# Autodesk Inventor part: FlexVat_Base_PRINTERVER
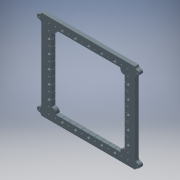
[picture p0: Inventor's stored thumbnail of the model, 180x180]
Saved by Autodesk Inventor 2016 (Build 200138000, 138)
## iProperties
Created: 2015-11
Part Number: FlexVat_Base_PRINTERVER
Material: Generic
Document SubType Name: Modeling
Designer: John
Density: 1 g/cm^3
Appearance: Default
Author: John
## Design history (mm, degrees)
feature "Base1"
sketch "Sketch1"
  geometry: L1 (212.7, 0)-(0, 0) reference; L2 (0, -20)-(0, -182.7) reference; L3 (0, -202.7)-(212.7, -202.7) reference; L4 (212.7, -20)-(212.7, -182.7) reference; L5 (18.082, -26.891)-(18.082, -26.392) reference; L6 (31.388, -189.618)-(31.888, -189.618) reference; L7 (180.808, -13.082)-(181.308, -13.082) reference; L8 (194.618, -26.392)-(194.618, -26.89) reference; L9 (189.575, -27.906)-(189.575, -41.33) reference; L10 (192.608, -41.33)-(189.575, -41.33) reference; L11 (189.575, -41.834)-(192.609, -41.834) reference; L12 (189.575, -41.834)-(189.575, -56.276) reference; L13 (194.617, -56.276)-(189.575, -56.276) reference; L14 (189.575, -56.776)-(194.619, -56.776) reference; L15 (189.575, -56.776)-(189.575, -71.214) reference; L16 (192.608, -71.214)-(189.575, -71.214) reference; L17 (189.575, -71.718)-(192.609, -71.718) reference; L18 (189.575, -71.718)-(189.575, -86.156) reference; L19 (189.575, -86.156)-(194.619, -86.156) reference; L20 (194.618, -86.66)-(189.575, -86.66) reference; L21 (189.575, -86.66)-(189.575, -101.102) reference; L22 (192.608, -101.102)-(189.575, -101.102) reference; L23 (189.575, -101.602)-(192.609, -101.602) reference; L24 (189.575, -101.602)-(189.575, -116.04) reference; L25 (189.575, -116.04)-(194.619, -116.04) reference; L26 (194.618, -116.544)-(189.575, -116.544) reference; L27 (189.575, -116.544)-(189.575, -130.982) reference; L28 (189.575, -130.982)-(192.609, -130.982) reference; L29 (192.608, -131.486)-(189.575, -131.486) reference; L30 (189.575, -131.486)-(189.575, -145.928) reference; L31 (189.575, -145.928)-(194.618, -145.928) reference; L32 (194.618, -146.428)-(189.575, -146.428) reference; L33 (189.575, -146.428)-(189.575, -160.866) reference; L34 (192.608, -160.866)-(189.575, -160.866) reference; L35 (189.575, -161.37)-(192.609, -161.37) reference; L36 (189.575, -161.37)-(189.575, -174.794) reference; L37 (179.794, -184.575)-(166.366, -184.575) reference; L38 (166.366, -184.575)-(166.366, -187.608) reference; L39 (165.866, -187.608)-(165.866, -184.575) reference; L40 (165.866, -184.575)-(151.424, -184.575) reference; L41 (151.424, -184.575)-(151.424, -189.618) reference; L42 (150.924, -189.618)-(150.924, -184.575) reference; L43 (150.924, -184.575)-(136.482, -184.575) reference; L44 (136.482, -184.575)-(136.482, -187.608) reference; L45 (135.982, -187.608)-(135.982, -184.575) reference; L46 (135.982, -184.575)-(121.54, -184.575) reference; L47 (121.54, -184.575)-(121.54, -189.618) reference; L48 (121.04, -189.618)-(121.04, -184.575) reference; L49 (121.04, -184.575)-(106.598, -184.575) reference; L50 (106.598, -184.575)-(106.598, -187.608) reference; L51 (106.098, -187.608)-(106.098, -184.575) reference; L52 (106.098, -184.575)-(91.656, -184.575) reference; L53 (91.656, -184.575)-(91.656, -189.618) reference; L54 (91.156, -189.618)-(91.156, -184.575) reference; L55 (91.156, -184.575)-(76.714, -184.575) reference; L56 (76.714, -184.575)-(76.714, -187.608) reference; L57 (76.214, -187.608)-(76.214, -184.575) reference; L58 (76.214, -184.575)-(61.772, -184.575) reference; L59 (61.772, -184.575)-(61.772, -189.618) reference; L60 (61.272, -189.618)-(61.272, -184.575) reference; L61 (61.272, -184.575)-(46.83, -184.575) reference; L62 (46.83, -184.575)-(46.83, -187.608) reference; L63 (46.33, -187.608)-(46.33, -184.575) reference; L64 (46.33, -184.575)-(32.906, -184.575) reference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; C1 r 1.75 at (16.7, -11.7) reference; C2 r 1.75 at (196, -11.7) reference; C3 r 1.75 at (217.7, -192.7) reference; C4 r 1.75 at (217.7, -10) reference; C5 r 1.75 at (-5, -10) reference; C6 r 1.75 at (-5, -192.7) reference; C7 r 1.75 at (196, -191) reference; C8 r 1.75 at (16.7, -191) reference; A1 r 5 centre (-5, 0) between (-5, -5) and (0, 0) reference; A2 r 5 centre (-5, -10) between (-5, -5) and (-5, -15) reference; A3 r 5 centre (-5, -20) between (0, -20) and (-5, -15) reference; A4 r 5 centre (-5, -182.7) between (-5, -187.7) and (0, -182.7) reference; A5 r 5 centre (-5, -192.7) between (-5, -187.7) and (-5, -197.7) reference; A6 r 5 centre (-5, -202.7) between (0, -202.7) and (-5, -197.7) reference; A7 r 5 centre (217.7, -202.7) between (217.7, -197.7) and (212.7, -202.7) reference; A8 r 5 centre (217.7, -192.7) between (217.7, -197.7) and (217.7, -187.7) reference; A9 r 5 centre (217.7, -182.7) between (212.7, -182.7) and (217.7, -187.7) reference; A10 r 5 centre (217.7, -20) between (217.7, -15) and (212.7, -20) reference; A11 r 5 centre (217.7, -10) between (217.7, -15) and (217.7, -5) reference; A12 r 5 centre (217.7, 0) between (212.7, 0) and (217.7, -5) reference; A13 r 1.75 centre (16.35, -26.642) between (18.082, -26.392) and (18.082, -26.891) reference; A14 r 1.75 centre (31.638, -191.35) between (31.388, -189.618) and (31.888, -189.618) reference; A15 r 1.75 centre (181.058, -11.35) between (181.308, -13.082) and (180.808, -13.082) reference; A16 r 1.75 centre (196.35, -26.642) between (194.618, -26.89) and (194.618, -26.392) reference; A17 r 8.125 centre (187.7, -20) between (179.794, -18.125) and (189.575, -27.906) reference; A18 r 3.75 centre (196.35, -41.58) between (192.609, -41.834) and (192.608, -41.33) reference; A19 r 1.75 centre (196.35, -56.522) between (194.619, -56.776) and (194.617, -56.276) reference; A20 r 3.75 centre (196.35, -71.464) between (192.609, -71.718) and (192.608, -71.214) reference; A21 r 1.75 centre (196.35, -86.41) between (194.618, -86.66) and (194.619, -86.156) reference; A22 r 3.75 centre (196.35, -101.348) between (192.609, -101.602) and (192.608, -101.102) reference; A23 r 1.75 centre (196.35, -116.294) between (194.618, -116.544) and (194.619, -116.04) reference; A24 r 3.75 centre (196.35, -131.236) between (192.608, -131.486) and (192.609, -130.982) reference; A25 r 1.75 centre (196.35, -146.178) between (194.618, -146.428) and (194.618, -145.928) reference; A26 r 3.75 centre (196.35, -161.116) between (192.609, -161.37) and (192.608, -160.866) reference; A27 r 8.125 centre (187.7, -182.7) between (189.575, -174.794) and (179.794, -184.575) reference; A28 r 3.75 centre (166.116, -191.35) between (165.866, -187.608) and (166.366, -187.608) reference; A29 r 1.75 centre (151.174, -191.35) between (150.924, -189.618) and (151.424, -189.618) reference; A30 r 3.75 centre (136.232, -191.35) between (135.982, -187.608) and (136.482, -187.608) reference; A31 r 1.75 centre (121.29, -191.35) between (121.04, -189.618) and (121.54, -189.618) reference; A32 r 3.75 centre (106.348, -191.35) between (106.098, -187.608) and (106.598, -187.608) reference; A33 r 1.75 centre (91.406, -191.35) between (91.156, -189.618) and (91.656, -189.618) reference; A34 r 3.75 centre (76.464, -191.35) between (76.214, -187.608) and (76.714, -187.608) reference; A35 r 1.75 centre (61.522, -191.35) between (61.272, -189.618) and (61.772, -189.618) reference; A36 r 3.75 centre (46.58, -191.35) between (46.33, -187.608) and (46.83, -187.608) reference; A37 r 8.125 centre (25, -182.7) between (32.906, -184.575) and (23.125, -174.794) reference; A38 r 3.75 centre (16.35, -161.116) between (20.092, -160.866) and (20.091, -161.37) reference; A39 r 1.75 centre (16.35, -146.174) between (18.082, -145.924) and (18.082, -146.424) reference; A40 r 3.75 centre (16.35, -131.236) between (20.091, -130.982) and (20.092, -131.486) reference; A41 r 1.75 centre (16.35, -116.294) between (18.081, -116.04) and (18.082, -116.544) reference; A42 r 3.75 centre (16.35, -101.348) between (20.092, -101.098) and (20.091, -101.602) reference; A43 r 1.75 centre (16.35, -86.406) between (18.083, -86.16) and (18.081, -86.66) reference; A44 r 3.75 centre (16.35, -71.464) between (20.092, -71.218) and (20.092, -71.714) reference; A45 r 1.75 centre (16.35, -56.522) between (18.082, -56.272) and (18.082, -56.772) reference; A46 r 3.75 centre (16.35, -41.58) between (20.092, -41.334) and (20.092, -41.83) reference; A47 r 8.125 centre (25, -20) between (23.125, -27.906) and (32.906, -18.125) reference; A48 r 3.75 centre (46.58, -11.35) between (46.83, -15.092) and (46.33, -15.092) reference; A49 r 1.75 centre (61.522, -11.35) between (61.772, -13.082) and (61.272, -13.082) reference; A50 r 3.75 centre (76.464, -11.35) between (76.714, -15.092) and (76.214, -15.092) reference; A51 r 1.75 centre (91.406, -11.35) between (91.656, -13.082) and (91.156, -13.082) reference; A52 r 3.75 centre (106.348, -11.35) between (106.598, -15.092) and (106.098, -15.092) reference; A53 r 1.75 centre (121.29, -11.35) between (121.54, -13.082) and (121.04, -13.082) reference; A54 r 3.75 centre (136.232, -11.35) between (136.482, -15.092) and (135.982, -15.092) reference; A55 r 1.75 centre (151.174, -11.35) between (151.424, -13.082) and (150.924, -13.082) reference; A56 r 3.75 centre (166.116, -11.35) between (166.366, -15.092) and (165.866, -15.092) reference; A57 r 1.75 centre (196.35, -176.058) between (194.618, -176.31) and (194.618, -175.808) reference; A58 r 1.75 centre (181.058, -191.35) between (180.808, -189.618) and (181.308, -189.618) reference; A59 r 1.75 centre (16.35, -176.058) between (18.082, -175.808) and (18.082, -176.308) reference; A60 r 1.75 centre (31.638, -11.35) between (31.888, -13.082) and (31.388, -13.082) reference; 1 further point
extrude "Extrusion1" join sketch "Sketch1" distance "d0" = 6; taper "d1" = 0 deg
sketch "Sketch2"
  geometry: L1 (212.7, 0)-(0, 0) reference; L2 (212.7, 20)-(212.7, 182.7) reference; L3 (0, 202.7)-(212.7, 202.7) reference; L4 (0, 20)-(0, 182.7) reference; L5 (181.312, 189.618)-(180.812, 189.618) reference; L6 (181.312, 13.082)-(180.812, 13.082) reference; L7 (18.082, 176.308)-(18.082, 175.81) reference; L8 (18.082, 26.39)-(18.082, 26.892) reference; L9 (194.618, 26.392)-(194.618, 26.892) reference; L10 (31.892, 189.618)-(31.392, 189.618) reference; L11 (32.906, 184.575)-(46.334, 184.575) reference; L12 (46.334, 184.575)-(46.334, 187.608) reference; L13 (46.834, 187.608)-(46.834, 184.575) reference; L14 (46.834, 184.575)-(61.276, 184.575) reference; L15 (61.276, 184.575)-(61.276, 189.618) reference; L16 (61.776, 189.618)-(61.776, 184.575) reference; L17 (61.776, 184.575)-(76.218, 184.575) reference; L18 (76.218, 184.575)-(76.218, 187.608) reference; L19 (76.718, 187.608)-(76.718, 184.575) reference; L20 (76.718, 184.575)-(91.16, 184.575) reference; L21 (91.16, 184.575)-(91.16, 189.618) reference; L22 (91.66, 189.618)-(91.66, 184.575) reference; L23 (91.66, 184.575)-(106.102, 184.575) reference; L24 (106.102, 184.575)-(106.102, 187.608) reference; L25 (106.602, 187.608)-(106.602, 184.575) reference; L26 (106.602, 184.575)-(121.044, 184.575) reference; L27 (121.044, 184.575)-(121.044, 189.618) reference; L28 (121.544, 189.618)-(121.544, 184.575) reference; L29 (121.544, 184.575)-(135.986, 184.575) reference; L30 (135.986, 184.575)-(135.986, 187.608) reference; L31 (136.486, 187.608)-(136.486, 184.575) reference; L32 (136.486, 184.575)-(150.928, 184.575) reference; L33 (150.928, 184.575)-(150.928, 189.618) reference; L34 (151.428, 189.618)-(151.428, 184.575) reference; L35 (151.428, 184.575)-(165.87, 184.575) reference; L36 (165.87, 184.575)-(165.87, 187.608) reference; L37 (166.37, 187.608)-(166.37, 184.575) reference; L38 (166.37, 184.575)-(179.794, 184.575) reference; L39 (189.575, 174.794)-(189.575, 161.366) reference; L40 (189.575, 161.366)-(192.608, 161.366) reference; L41 (192.608, 160.87)-(189.575, 160.87) reference; L42 (189.575, 160.87)-(189.575, 146.428) reference; L43 (189.575, 146.428)-(194.618, 146.428) reference; L44 (194.618, 145.928)-(189.575, 145.928) reference; L45 (189.575, 145.928)-(189.575, 131.482) reference; L46 (192.608, 131.482)-(189.575, 131.482) reference; L47 (189.575, 130.986)-(192.608, 130.986) reference; L48 (189.575, 130.986)-(189.575, 116.54) reference; L49 (189.575, 116.54)-(194.617, 116.54) reference; L50 (194.619, 116.04)-(189.575, 116.04) reference; L51 (189.575, 116.04)-(189.575, 101.602) reference; L52 (189.575, 101.602)-(192.608, 101.602) reference; L53 (192.609, 101.098)-(189.575, 101.098) reference; L54 (189.575, 101.098)-(189.575, 86.66) reference; L55 (189.575, 86.66)-(194.619, 86.66) reference; L56 (194.618, 86.156)-(189.575, 86.156) reference; L57 (189.575, 86.156)-(189.575, 71.718) reference; L58 (192.609, 71.718)-(189.575, 71.718) reference; L59 (189.575, 71.214)-(192.608, 71.214) reference; L60 (189.575, 71.214)-(189.575, 56.776) reference; L61 (189.575, 56.776)-(194.618, 56.776) reference; L62 (194.618, 56.276)-(189.575, 56.276) reference; L63 (189.575, 56.276)-(189.575, 41.834) reference; L64 (192.608, 41.834)-(189.575, 41.834) reference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; C1 r 1.75 at (16.7, 191) reference; C2 r 1.75 at (196, 191) reference; C3 r 1.75 at (196, 11.7) reference; C4 r 1.75 at (16.7, 11.7) reference; C5 r 1.75 at (-5, 10) reference; C6 r 1.75 at (-5, 192.7) reference; C7 r 1.75 at (217.7, 192.7) reference; C8 r 1.75 at (217.7, 10) reference; C9 r 2 at (-5, 192.7); C10 r 2 at (-5, 10); C11 r 2 at (217.7, 10); C12 r 2 at (217.7, 192.7); A1 r 5 centre (217.7, 0) between (217.7, 5) and (212.7, 0) reference; A2 r 5 centre (217.7, 10) between (217.7, 5) and (217.7, 15) reference; A3 r 5 centre (217.7, 20) between (212.7, 20) and (217.7, 15) reference; A4 r 5 centre (217.7, 182.7) between (217.7, 187.7) and (212.7, 182.7) reference; A5 r 5 centre (217.7, 192.7) between (217.7, 187.7) and (217.7, 197.7) reference; A6 r 5 centre (217.7, 202.7) between (212.7, 202.7) and (217.7, 197.7) reference; A7 r 5 centre (-5, 202.7) between (-5, 197.7) and (0, 202.7) reference; A8 r 5 centre (-5, 192.7) between (-5, 197.7) and (-5, 187.7) reference; A9 r 5 centre (-5, 182.7) between (0, 182.7) and (-5, 187.7) reference; A10 r 5 centre (-5, 20) between (-5, 15) and (0, 20) reference; A11 r 5 centre (-5, 10) between (-5, 15) and (-5, 5) reference; A12 r 5 centre (-5, 0) between (0, 0) and (-5, 5) reference; A13 r 1.75 centre (181.062, 191.35) between (181.312, 189.618) and (180.812, 189.618) reference; A14 r 1.75 centre (181.062, 11.35) between (180.812, 13.082) and (181.312, 13.082) reference; A15 r 1.75 centre (16.35, 176.058) between (18.082, 176.308) and (18.082, 175.81) reference; A16 r 1.75 centre (16.35, 26.642) between (18.082, 26.892) and (18.082, 26.39) reference; A17 r 1.75 centre (196.35, 26.642) between (194.618, 26.392) and (194.618, 26.892) reference; A18 r 1.75 centre (31.642, 191.35) between (31.892, 189.618) and (31.392, 189.618) reference; A19 r 8.125 centre (25, 182.7) between (23.125, 174.794) and (32.906, 184.575) reference; A20 r 3.75 centre (46.584, 191.35) between (46.834, 187.608) and (46.334, 187.608) reference; A21 r 1.75 centre (61.526, 191.35) between (61.776, 189.618) and (61.276, 189.618) reference; A22 r 3.75 centre (76.468, 191.35) between (76.718, 187.608) and (76.218, 187.608) reference; A23 r 1.75 centre (91.41, 191.35) between (91.66, 189.618) and (91.16, 189.618) reference; A24 r 3.75 centre (106.352, 191.35) between (106.602, 187.608) and (106.102, 187.608) reference; A25 r 1.75 centre (121.294, 191.35) between (121.544, 189.618) and (121.044, 189.618) reference; A26 r 3.75 centre (136.236, 191.35) between (136.486, 187.608) and (135.986, 187.608) reference; A27 r 1.75 centre (151.178, 191.35) between (151.428, 189.618) and (150.928, 189.618) reference; A28 r 3.75 centre (166.12, 191.35) between (166.37, 187.608) and (165.87, 187.608) reference; A29 r 8.125 centre (187.7, 182.7) between (179.794, 184.575) and (189.575, 174.794) reference; A30 r 3.75 centre (196.35, 161.12) between (192.608, 160.87) and (192.608, 161.366) reference; A31 r 1.75 centre (196.35, 146.178) between (194.618, 145.928) and (194.618, 146.428) reference; A32 r 3.75 centre (196.35, 131.236) between (192.608, 130.986) and (192.608, 131.482) reference; A33 r 1.75 centre (196.35, 116.294) between (194.619, 116.04) and (194.617, 116.54) reference; A34 r 3.75 centre (196.35, 101.352) between (192.609, 101.098) and (192.608, 101.602) reference; A35 r 1.75 centre (196.35, 86.406) between (194.618, 86.156) and (194.619, 86.66) reference; A36 r 3.75 centre (196.35, 71.464) between (192.608, 71.214) and (192.609, 71.718) reference; A37 r 1.75 centre (196.35, 56.526) between (194.618, 56.276) and (194.618, 56.776) reference; A38 r 3.75 centre (196.35, 41.584) between (192.609, 41.33) and (192.608, 41.834) reference; A39 r 8.125 centre (187.7, 20) between (189.575, 27.906) and (179.794, 18.125) reference; A40 r 3.75 centre (166.12, 11.35) between (165.87, 15.092) and (166.37, 15.092) reference; A41 r 1.75 centre (151.178, 11.35) between (150.928, 13.082) and (151.428, 13.082) reference; A42 r 3.75 centre (136.236, 11.35) between (135.986, 15.092) and (136.486, 15.092) reference; A43 r 1.75 centre (121.294, 11.35) between (121.044, 13.082) and (121.544, 13.082) reference; A44 r 3.75 centre (106.352, 11.35) between (106.102, 15.092) and (106.602, 15.092) reference; A45 r 1.75 centre (91.41, 11.35) between (91.16, 13.082) and (91.66, 13.082) reference; A46 r 3.75 centre (76.468, 11.35) between (76.218, 15.092) and (76.718, 15.092) reference; A47 r 1.75 centre (61.526, 11.35) between (61.276, 13.082) and (61.776, 13.082) reference; A48 r 3.75 centre (46.584, 11.35) between (46.334, 15.092) and (46.834, 15.092) reference; A49 r 8.125 centre (25, 20) between (32.906, 18.125) and (23.125, 27.906) reference; A50 r 3.75 centre (16.35, 41.584) between (20.092, 41.834) and (20.091, 41.33) reference; A51 r 1.75 centre (16.35, 56.522) between (18.082, 56.772) and (18.082, 56.272) reference; A52 r 3.75 centre (16.35, 71.464) between (20.091, 71.718) and (20.092, 71.214) reference; A53 r 1.75 centre (16.35, 86.406) between (18.081, 86.66) and (18.082, 86.156) reference; A54 r 3.75 centre (16.35, 101.352) between (20.092, 101.598) and (20.091, 101.098) reference; A55 r 1.75 centre (16.35, 116.29) between (18.081, 116.544) and (18.082, 116.04) reference; A56 r 3.75 centre (16.35, 131.236) between (20.092, 131.486) and (20.091, 130.982) reference; A57 r 1.75 centre (16.35, 146.178) between (18.083, 146.424) and (18.081, 145.924) reference; A58 r 3.75 centre (16.35, 161.12) between (20.092, 161.37) and (20.091, 160.866) reference; A59 r 1.75 centre (196.35, 176.058) between (194.618, 175.809) and (194.618, 176.308) reference; A60 r 1.75 centre (31.642, 11.35) between (31.392, 13.082) and (31.892, 13.082) reference; 1 further point
  constraints: 4 centre point, 3 equal radius
  dimensions: "d2" = 4 diameter of C9
extrude "Extrusion2" cut sketch "Sketch2" stored distance "d3" = 6; taper "d4" = 0 deg
body "Solid1"
node "Projected Loop1"
node "Projected Loop2"
